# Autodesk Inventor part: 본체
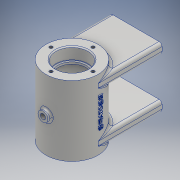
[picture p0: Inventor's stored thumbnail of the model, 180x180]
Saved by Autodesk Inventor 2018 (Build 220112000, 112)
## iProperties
Created: 2020-07
Part Number: 본체
Material: 알루미늄 6061
Document SubType Name: Modeling
Designer: home
Density: 2.7 g/cm^3
Appearance: 알루미늄 - 평지
Mass: 305.056 g
Surface Area: 358.163 cm^2
Volume: 112.984 cm^3
Author: home
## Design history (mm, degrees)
sketch "스케치1"
  geometry: L1 (16, 35)-(16, 23); L2 (16, 23)-(14, 23); L3 (14, 23)-(14, 21); L4 (14, 21)-(21, 21); L5 (21, 21)-(21, -21); L6 (21, -21)-(14, -21); L7 (14, -21)-(14, -23); L8 (14, -23)-(16, -23); L9 (16, -23)-(16, -35); L10 (0, -35)-(0, 35); L11 (16, 35)-(26, 35); L12 (26, 35)-(26, -35); L13 (26, -35)-(16, -35); 3 further points
  constraints: 26 end point, 8 perpendicular, 2 coincident, 2 horizontal, 2 point on line, 2 vertical, 1 midpoint
  dimensions: "d2" = 2 distance of L2.end L3.end; "d4" = 42 distance of L4.end L5.end; "d5" = 2 distance of L6.end L7.end; "d6" = 12 distance of L8.end L9.end; "d8" = 70 distance of L10.start L10.end; "d11" = 32 diameter of L1 L10; "d12" = 52 diameter of L12 L10; "d13" = 42 diameter of L5 L10; "d14" = 10 distance of L12.end L9.end; "d15" = 2 distance of L7.end L8.end; "d16" = 70 distance between parallel lines of L13 L11; "d17" = 35 distance from line of point (0, 0) L11
revolve "회전1" sketch "스케치1" stored, may be unused: angle "d18" = 90 deg
node "작업 평면1"
sketch "스케치2"
  geometry: 1 further point
sketch "스케치3"
  geometry: L1 (-26, -30)-(26, -30); L2 (26, -30)-(26, -20); L3 (26, -20)-(-26, -20); L4 (-26, -20)-(-26, -30); L5 (-26, 35)-(26, 35) reference; L6 (-26, -35)-(26, -35) reference; L7 (-26, 35)-(-26, -35) reference; 1 further point
  constraints: 8 end point, 2 parallel, 1 horizontal, 1 perpendicular
  dimensions: "d20" = 52 distance of L3.end L2.end; "d21" = 10 distance of L2.end L1.end; "d22" = 20 distance from line of L3 point (0, 0); "d23" = 0 distance between parallel lines of L4 L7
extrude "돌출1" join sketch "스케치3" stored distance "d24" = 10; taper "d25" = 0 deg
sketch "스케치4" dims "d26" = 42
  geometry: 3 further points
  constraints: 2 vertical alignment, 1 coincident, 2 other
  dimensions: "d88" = 21 distance of point (0, -21) point (0, 0) (derived)
hole "구멍1" sketch "스케치4" at (0, -21) diameter "d27" = 3.242; stored, may be unused: countersink angle "d31" = 90 deg, drill point angle "d33" = 118 deg; dims "d28" = 8, "d29" = 4, "d30" = 2, "d32" = 10
node "작업 평면2"
sketch "스케치6"
  geometry: C1 r 5 at (0, 0); 1 further point
  constraints: 1 centre point, 1 coincident
  dimensions: "d38" = 10 diameter of C1
extrude "돌출2" join sketch "스케치6" stored distance "d39" = 10 (= d38); taper "d40" = 0 deg
sketch "스케치7"
  geometry: 1 further point
hole "구멍2" sketch "스케치7" at (0, 0) diameter "d41" = 5.188; stored, may be unused: countersink angle "d45" = 90 deg, drill point angle "d47" = 118 deg; dims "d42" = 12, "d43" = 4, "d44" = 2, "d46" = 16
node "작업 평면4"
sketch "스케치11"
  geometry: L1 (-26, -35)-(26, -35) reference; L2 (0, -14.175)-(0, -3.309); L3 (0, -3.309)-(36.054, -3.309); L4 (36.054, -3.309)-(36.054, -14.175); L5 (36.054, -14.175)-(0, -14.175); 1 further point
  constraints: 2 other
  dimensions: "d53" = 35 distance from line of L1 point (0, 0) (derived); "d54" = 26 horizontal distance of L2.end L1.start
feature "엠보싱1" sketch "스케치11" dims "d20" = 52, "d21" = 10, "d22" = 20, "d23" = 0, "d55" = 1, "d56" = 0
fillet "모깎기1" dims "d57" = 3, "d58" = 3, "d59" = 3, "d60" = 0.3, "d81" = 2
chamfer "모따기1" distance "d62" = 1; stored, may be unused: second distance "d63" = 2, angle "d64" = 45 deg
sketch "스케치12"
  geometry: 2 further points
  dimensions: "d65" = 20 horizontal distance of point (3, 5) point (23, 30)
hole "구멍3" sketch "스케치12" at (3, 5) diameter "d66" = 4.134; stored, may be unused: countersink angle "d70" = 90 deg, drill point angle "d72" = 118 deg; dims "d67" = 8, "d68" = 4, "d69" = 2, "d71" = 10
sketch "스케치14"
  geometry: C1 r 5 at (0, 0); C2 r 6 at (0, 0); 1 further point
  constraints: 2 centre point, 2 coincident
  dimensions: "d82" = 10 diameter of C1; "d83" = 12 diameter of C2
extrude "돌출3" join sketch "스케치14" stored distance "d84" = 10; taper "d85" = 0 deg
fillet "모깎기2" dims "d87" = 2
node "솔리드1"
mirror "미러1"
pattern_circular "원형 패턴1" dims angle "d35" = 360 deg
mirror "미러2"
pattern_circular "원형 패턴2" dims angle "d49" = 160 deg
pattern_linear "직사각형 패턴1" dims "d75" = 40, "d78" = 50
node "투영된 루프1"
other parameters: "d19" = 64, "d37" = -29, "d52" = 26
